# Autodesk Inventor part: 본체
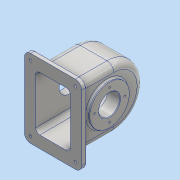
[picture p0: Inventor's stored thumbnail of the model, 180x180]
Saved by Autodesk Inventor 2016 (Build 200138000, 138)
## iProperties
Created: 2018-11
Part Number: 본체
Material: 알루미늄 6061
Document SubType Name: Modeling
Designer: user
Mass: 1092.08 g
Surface Area: 1182.21 cm^2
Volume: 404.475 cm^3
Density: 2.7 g/cm^3
Appearance: 알루미늄 - 평지
Author: user
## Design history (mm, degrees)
sketch "스케치1"
  geometry: L1 (55, 75)-(-55, 75); L2 (-55, 75)-(-55, -75); L3 (-55, -75)-(55, -75); L4 (55, -75)-(55, 75); L5 (55, 75)-(-55, -75); L6 (-55, 75)-(55, -75); 1 further point
  constraints: 12 end point, 2 midpoint, 2 parallel, 1 horizontal, 1 perpendicular
  dimensions: "d0" = 110 distance of L3.end L2.end; "d1" = 150 distance of L2.end L1.end
extrude "돌출1" new body sketch "스케치1" distance "d2" = 10; taper "d3" = 0 deg
sketch "스케치2"
  geometry: L1 (-38.5, -58)-(38.5, -58); L2 (38.5, -58)-(38.5, 58); L3 (38.5, 58)-(-38.5, 58); L4 (-38.5, 58)-(-38.5, -58); L5 (-38.5, -58)-(38.5, 58); L6 (38.5, -58)-(-38.5, 58); 1 further point
  constraints: 12 end point, 2 midpoint, 2 parallel, 1 horizontal, 1 perpendicular
  dimensions: "d4" = 77 distance of L3.end L2.end; "d5" = 116 distance of L2.end L1.end
extrude "돌출2" join sketch "스케치2" distance "d6" = 68; taper "d7" = 0 deg
sketch "스케치3"
  geometry: L1 (116, 68)-(0, 68) reference; L2 (0, 68)-(116, 68); A1 r 58 centre (58, 68) between (116, 68) and (0, 68); 1 further point
  constraints: 2 end point, 2 point on circle, 1 centre point, 1 collinear, 1 midpoint
extrude "돌출3" join sketch "스케치3" distance "d8" = 77; taper "d9" = 0 deg
feature "쉘1" dims "d10" = 6, "d11" = 10, "d12" = 5
sketch "스케치4"
  geometry: L1 (-17, -10)-(133, -10) reference; C1 r 38 at (58, 55); 2 further points
  constraints: 1 centre point, 1 midpoint, 1 vertical alignment
  dimensions: "d13" = 76 diameter of C1; "d14" = 65 distance from line of L1 C1.centre
extrude "돌출4" join sketch "스케치4" distance "d15" = 5; taper "d16" = 0 deg
sketch "스케치8"
  geometry: L1 (-17, -10)-(133, -10) reference; C1 r 38 at (58, 55); 2 further points
  constraints: 1 centre point, 1 midpoint, 1 vertical alignment
  dimensions: "d34" = 76 diameter of C1; "d35" = 65 distance from line of L1 C1.centre
extrude "돌출7" join sketch "스케치8" distance "d36" = 10; taper "d37" = 0 deg
sketch "스케치9"
  geometry: L1 (33.5, 104.747)-(33.5, 65); L2 (33.5, 65)-(19.5, 65); L3 (19.5, 65)-(19.5, 93); L4 (19.5, 93)-(33.5, 104.747); L5 (33.5, 130)-(33.5, 78) reference; L6 (43.5, 27)-(43.5, 103) reference; 1 further point
  constraints: 8 end point, 2 perpendicular, 1 collinear, 1 vertical
  dimensions: "d38" = 65 distance from line of point (0, 0) L2; "d39" = 24 distance between parallel lines of L6 L3; "d40" = 28 distance of L2.end L3.end; "d41" = 50 deg angle of L4 L3
revolve "회전1" sketch "스케치9" stored, may be unused: angle "d42" = 90 deg
sketch "스케치10"
  geometry: C1 r 38 at (0, 0) reference; C2 r 20 at (0, 0); 1 further point
  constraints: 1 centre point, 1 coincident
  dimensions: "d43" = 40 diameter of C2
extrude "돌출8" cut sketch "스케치10" stored distance "d44" = 10; taper "d45" = 0 deg
sketch "스케치11"
  geometry: C1 r 38 at (0, 0) reference; 2 further points
  constraints: 1 vertical alignment
  dimensions: "d46" = 29 distance of C1.centre point (0, 29)
hole "구멍2" sketch "스케치11" at (0, 29) diameter "d47" = 3.242; stored, may be unused: countersink angle "d51" = 90 deg, drill point angle "d53" = 118 deg; dims "d48" = 8, "d49" = 4, "d50" = 2, "d52" = 10
sketch "스케치12"
  geometry: C1 r 38 at (0, 0) reference; 2 further points
  constraints: 1 vertical alignment
  dimensions: "d57" = 29 distance of C1.centre point (0, 29)
hole "구멍3" sketch "스케치12" at (0, 29) diameter "d58" = 3.242; stored, may be unused: countersink angle "d62" = 90 deg, drill point angle "d64" = 118 deg; dims "d59" = 8, "d60" = 4, "d61" = 2, "d63" = 10
node "작업 평면1"
sketch "스케치13"
  geometry: C1 r 6 at (0, 0); 1 further point
  constraints: 1 centre point, 1 coincident
  dimensions: "d69" = 12 diameter of C1
extrude "돌출9" join sketch "스케치13" stored distance "d70" = 10; taper "d71" = 5 deg
fillet "모깎기1" dims "d79" = 12
sketch "스케치15"
  geometry: C1 r 6 at (43, 63); A1 r 12 centre (43, 63) between (55, 63) and (43, 75) reference; 1 further point
  constraints: 1 centre point, 1 coincident
  dimensions: "d80" = 12 diameter of C1
extrude "돌출10" cut sketch "스케치15" distance "d81" = 4; taper "d82" = 0 deg
sketch "스케치16"
  geometry: C1 r 6 at (0, 0) reference; C2 r 2.5 at (0, 0); 1 further point
  constraints: 1 centre point, 1 coincident
  dimensions: "d83" = 5 diameter of C2
extrude "돌출11" cut sketch "스케치16" stored distance "d84" = 0; taper "d85" = 0 deg
chamfer "모따기1" distance "d86" = 1; stored, may be unused: second distance "d87" = 2, angle "d88" = 45 deg
fillet "모깎기2" dims "d89" = 13
fillet "모깎기3" dims "d90" = 8
fillet "모깎기4" dims "d91" = 3
sketch "스케치17"
  geometry: L1 (-17.5, -78)-(-29.5, -78) reference; L2 (-13, 0)-(-13, -65) reference; 2 further points
  constraints: 1 other
  dimensions: "d92" = 40 distance from line of L1 point (25.5, -38); "d93" = 38.5 distance from line of L2 point (25.5, -38)
feature "엠보싱1" sketch "스케치17" dims "d0" = 110, "d1" = 150, "d94" = 0.5, "d95" = 0
sketch "스케치18"
  geometry: 2 further points
  constraints: 1 coincident
hole "구멍5" sketch "스케치18" at (0, 0) diameter "d96" = 4.459; stored, may be unused: countersink angle "d100" = 90 deg, drill point angle "d102" = 118 deg; dims "d97" = 20, "d98" = 4, "d99" = 2, "d101" = 20
fillet "모깎기5" dims "d103" = 3
fillet "모깎기6" dims "d104" = 3
node "솔리드1"
pattern_circular "원형 패턴2" dims angle "d55" = 360 deg
pattern_circular "원형 패턴3" dims angle "d66" = 360 deg
mirror "대칭1"
mirror "대칭2"
other parameters: "d68" = 142
